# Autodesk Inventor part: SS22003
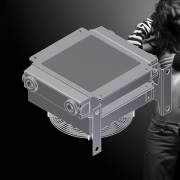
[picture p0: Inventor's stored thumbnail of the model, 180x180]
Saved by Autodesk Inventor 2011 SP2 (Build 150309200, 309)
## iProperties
Created: 2015-12
Part Number: SS22003
Material: Сталь
Document SubType Name: Modeling
Designer: Дорохин
Mass: 7000 g
Surface Area: 5612.32 cm^2
Volume: 4411.6 cm^3
Density: 1.58673 g/cm^3
Author: Дорохин
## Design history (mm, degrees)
derived "374_SS2200300A-PE.iam"
sketch "Эскиз2"
  geometry: L1 (230, 0)-(0, 0) reference; L2 (-25, -216.5)-(-25, -16.5) reference; L3 (0, -233)-(230, -233) reference; L4 (255, -16.5)-(255, -216.5) reference; L5 (20, -218)-(210, -218); L6 (215, -213)-(215, -20); L7 (210, -15)-(20, -15); L8 (15, -20)-(15, -213); A1 r 5 centre (20, -213) between (15, -213) and (20, -218); A2 r 5 centre (20, -20) between (20, -15) and (15, -20); A3 r 5 centre (210, -20) between (215, -20) and (210, -15); A4 r 5 centre (210, -213) between (210, -218) and (215, -213); 1 further point
  constraints: 8 end point, 8 point on circle, 8 tangent, 4 centre point, 3 equal radius, 2 parallel, 1 horizontal, 1 perpendicular
  dimensions: "d1" = 40 distance between parallel lines of L4 L6; "d2" = 40 distance between parallel lines of L2 L8 (= d1); "d3" = 15 distance between parallel lines of L3 L5; "d4" = 15 distance between parallel lines of L1 L7 (= d3); "d5" = 5 radius of A1
extrude "Выдавливание1" cut sketch "Эскиз2" distance "d6" = 2; taper "d7" = 0 deg
feature "Резьба1" dims "d8" = 10, "d9" = 0
feature "Резьба2" dims "d10" = 10, "d11" = 0
feature "Резьба3" dims "d12" = 10, "d13" = 0
node "Твердое тело1"
node "None.ipt:1"
node "None_1.ipt:1"
feature "Производный составной элемент1"
